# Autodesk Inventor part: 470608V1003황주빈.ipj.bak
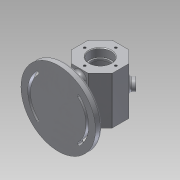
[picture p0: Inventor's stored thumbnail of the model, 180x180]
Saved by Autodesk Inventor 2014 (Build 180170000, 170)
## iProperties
Created: 2017-06
Part Number: 470608V1003황주빈.ipj.bak
Material: Aluminum 6061
Document SubType Name: Modeling
Designer: user
Density: 2.71 g/cm^3
Appearance: Aluminum - Flat
Author: user
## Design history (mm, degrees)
sketch "Sketch2"
  geometry: C1 r 55 at (0, 0); 1 further point
  constraints: 1 centre point, 1 coincident
extrude "Extrusion1" new body sketch "Sketch2" distance "d0" = 10; taper "d1" = 0 deg
sketch "Sketch3"
  geometry: L1 (-55, 0)-(-55, 10) reference; L2 (-55, 10)-(55, 10) reference; L3 (55, 10)-(55, 0) reference; L4 (55, 0)-(-55, 0) reference; L5 (0, 0)-(0, 62); L6 (12.426, 92)-(30, 74.426); L7 (30, 74.426)-(30, 49.574); L8 (30, 49.574)-(12.426, 32); L9 (12.426, 32)-(-12.426, 32); L10 (-12.426, 32)-(-30, 49.574); L11 (-30, 49.574)-(-30, 74.426); L12 (-30, 74.426)-(-12.426, 92); L13 (-12.426, 92)-(12.426, 92); 2 further points
  constraints: 18 end point, 1 midpoint, 17 other
extrude "Extrusion2" join sketch "Sketch3" stored distance "d2" = 70; taper "d3" = 0 deg
sketch "Sketch4"
  geometry: L1 (0, 55)-(10, 55) reference; L2 (10, 55)-(10, -55) reference; L3 (10, -55)-(0, -55) reference; L4 (0, -55)-(0, 55) reference; L5 (92, -35)-(32, -35) reference; L6 (32, -35)-(32, 35) reference; L7 (32, 35)-(92, 35) reference; L8 (92, 35)-(92, -35) reference; L9 (62, 35)-(62, -35); L10 (62, 35)-(78, 35); L11 (78, 35)-(78, 23.3); L12 (76, 23)-(76, 20); L13 (87, 17)-(87, -17); L14 (84, -20)-(76, -20); L15 (76, -20)-(76, -23); L16 (76, -23)-(77.7, -23); L17 (78, -23.3)-(78, -35); L18 (77.7, 23)-(76, 23); L19 (84, 20)-(76, 20); L20 (78, -35)-(62, -35); L21 (62, 35)-(62, -35); A1 r 0.3 centre (77.7, 23.3) between (77.7, 23) and (78, 23.3); A2 r 0.3 centre (77.7, -23.3) between (78, -23.3) and (77.7, -23); A3 r 3 centre (84, 17) between (87, 17) and (84, 20); A4 r 3 centre (84, -17) between (84, -20) and (87, -17); 1 further point
  constraints: 26 end point, 8 point on circle, 8 tangent, 4 centre point, 2 equal radius, 2 midpoint, 2 point on line
  dimensions: "d4" = 0.3 radius of A1; "d5" = 3 radius of A3
revolve "Revolution1" sketch "Sketch4" stored, may be unused: angle "d6" = 90 deg
sketch "Sketch6"
  geometry: L1 (0, 0)-(55, 0.071); L2 (0, 0)-(26.836, 26.905); L3 (33.898, 33.985)-(44.934, 45.049); L4 (26.905, -26.836)-(0, 0); L5 (0, 0)-(26.905, -26.836); L6 (33.985, -33.898)-(47.581, -47.459); L7 (47.581, -47.459)-(33.985, -33.898); L8 (-38.83, -38.952)-(-48.246, -48.396); L9 (0, 0)-(-26.828, -26.912); L10 (0, 0)-(-38, -0.059); L11 (0, 0)-(-26.912, 26.828); A1 r 55 centre (0, 0) between (55, 0.071) and (-38.83, -38.952) reference; A2 r 2 centre (-30.358, -30.453) between (-31.77, -31.869) and (-28.946, -29.037); A3 r 2 centre (-30.453, 30.358) between (-29.037, 28.946) and (-31.869, 31.77); A4 r 2 centre (30.445, -30.367) between (29.029, -28.954) and (31.861, -31.779); A5 r 2 centre (30.367, 30.445) between (31.779, 31.861) and (28.954, 29.029); A6 r 5 centre (30.367, 30.445) between (33.898, 33.985) and (26.836, 26.905); A7 r 41 centre (0, 0) between (29.029, -28.954) and (28.954, 29.029); A8 r 45 centre (0, 0) between (31.861, -31.779) and (31.779, 31.861); A9 r 5 centre (30.445, -30.367) between (26.905, -26.836) and (33.985, -33.898); A10 r 5 centre (-30.358, -30.453) between (-33.888, -33.994) and (-26.828, -26.912); A11 r 41 centre (0, 0) between (-29.037, 28.946) and (-28.946, -29.037); A12 r 45 centre (0, 0) between (-31.869, 31.77) and (-31.77, -31.869); A13 r 5 centre (-30.453, 30.358) between (-26.912, 26.828) and (-33.994, 33.888); A14 r 38 centre (0, 0) between (-26.912, 26.828) and (-26.828, -26.912); A15 r 38 centre (0, 0) between (26.905, -26.836) and (26.836, 26.905); A16 r 48 centre (0, 0) between (-33.994, 33.888) and (-33.888, -33.994); A17 r 48 centre (0, 0) between (33.985, -33.898) and (33.898, 33.985); 1 further point
  constraints: 35 point on circle, 22 end point, 16 centre point, 9 coincident, 2 other
extrude "Extrusion3" cut sketch "Sketch6" distance "d11" = 3; taper "d12" = 0 deg
sketch "Sketch7"
  geometry: C1 r 55 at (0, 0) reference; A1 r 41 centre (0, 0) between (-29.037, 28.946) and (-28.946, -29.037) reference; A2 r 2 centre (-30.358, -30.453) between (-31.77, -31.869) and (-28.946, -29.037) reference; A3 r 45 centre (0, 0) between (-31.869, 31.77) and (-31.77, -31.869) reference; A4 r 2 centre (-30.453, 30.358) between (-29.037, 28.946) and (-31.869, 31.77) reference; A5 r 5 centre (-30.453, 30.358) between (-26.912, 26.828) and (-33.994, 33.888) reference; A6 r 48 centre (0, 0) between (-33.994, 33.888) and (-33.888, -33.994) reference; A7 r 5 centre (-30.358, -30.453) between (-33.888, -33.994) and (-26.828, -26.912) reference; A8 r 38 centre (0, 0) between (-26.912, 26.828) and (-26.828, -26.912) reference; A9 r 41 centre (0, 0) between (29.029, -28.954) and (28.954, 29.029) reference; A10 r 2 centre (30.367, 30.445) between (31.779, 31.861) and (28.954, 29.029) reference; A11 r 45 centre (0, 0) between (31.861, -31.779) and (31.779, 31.861) reference; A12 r 2 centre (30.445, -30.367) between (29.029, -28.954) and (31.861, -31.779) reference; A13 r 5 centre (30.367, 30.445) between (33.898, 33.985) and (26.836, 26.905) reference; A14 r 38 centre (0, 0) between (26.905, -26.836) and (26.836, 26.905) reference; A15 r 5 centre (30.445, -30.367) between (26.905, -26.836) and (33.985, -33.898) reference; A16 r 48 centre (0, 0) between (33.985, -33.898) and (33.898, 33.985) reference; A17 r 2 centre (-30.358, -30.453) between (-31.77, -31.869) and (-28.946, -29.037); A18 r 2 centre (-30.453, 30.358) between (-29.037, 28.946) and (-31.869, 31.77); A19 r 2 centre (30.367, 30.445) between (31.779, 31.861) and (28.954, 29.029); A20 r 2 centre (30.445, -30.367) between (29.029, -28.954) and (31.861, -31.779); A21 r 45 centre (0, 0) between (31.861, -31.779) and (31.779, 31.861); A22 r 45 centre (0, 0) between (-31.869, 31.77) and (-31.77, -31.869); A23 r 41 centre (0, 0) between (29.029, -28.954) and (28.954, 29.029); A24 r 41 centre (0, 0) between (-29.037, 28.946) and (-28.946, -29.037)
  constraints: 16 point on circle, 8 centre point, 6 coincident
extrude "Extrusion4" cut sketch "Sketch7" stored distance "d13" = 3; taper "d14" = 0 deg
workplane "Work Plane1"
sketch "Sketch8"
  geometry: L1 (8.551, 10.352)-(8.551, 60.127); L2 (8.551, 60.127)-(15.756, 60.127); L3 (15.756, 60.127)-(15.756, 10.352); L4 (15.756, 10.352)-(8.551, 10.352); L5 (24.853, 0)-(0, 0) reference; 2 further points
  constraints: 1 point on line, 2 other
emboss "Emboss1" sketch "Sketch8" dims "d16" = 0.5, "d17" = 0
sketch "Sketch9"
  geometry: L1 (-5, -24)-(-5, 24); L2 (5, 24)-(5, -24); A1 r 5 centre (0, -24) between (-5, -24) and (5, -24); A2 r 5 centre (0, 24) between (5, 24) and (-5, 24)
  constraints: 4 end point, 4 point on circle, 2 centre point
extrude "Extrusion5" join sketch "Sketch9" stored distance "d18" = 3; taper "d19" = 0 deg
fillet "Fillet1" dims "d20" = 5
workplane "Work Plane2"
sketch "Sketch10"
  geometry: L1 (-24.853, 70)-(0, 70) reference; L2 (-12.426, 70)-(-12.426, 35); C1 r 8 at (-12.426, 35); 1 further point
  constraints: 2 end point, 1 centre point, 1 coincident, 1 midpoint
extrude "Extrusion6" join sketch "Sketch10" stored distance "d22" = 3; taper "d23" = 0 deg
sketch "Sketch11"
  geometry: C1 r 8 at (0, 0) reference; 2 further points
  constraints: 1 coincident
hole "Hole1" sketch "Sketch11" at (0, 0) diameter "d24" = 8; stored, may be unused: countersink angle "d28" = 90 deg, drill point angle "d30" = 118 deg; dims "d25" = 6, "d26" = 4, "d27" = 2, "d29" = 30
chamfer "Chamfer1" distance "d31" = 1; stored, may be unused: second distance "d32" = 2, angle "d33" = 45 deg
fillet "Fillet2" dims "d34" = 3
sketch "Sketch12"
  geometry: L1 (-32.438, 7)-(-28.279, 7) reference; L2 (-28.279, 7)-(-28.279, 10) reference; L3 (-28.279, 10)-(28.566, 10) reference; L4 (28.566, 10)-(28.566, 7) reference; L5 (28.566, 7)-(32.324, 7) reference; L6 (32.324, 7)-(32.324, 10) reference; L7 (32.324, 10)-(42.426, 10) reference; L8 (42.426, 10)-(42.426, 0) reference; L9 (42.426, 0)-(-42.426, 0) reference; L10 (-42.426, 0)-(-42.426, 10) reference; L11 (-42.426, 10)-(-32.438, 10) reference; L12 (-32.438, 10)-(-32.438, 7) reference; L13 (-12.426, 32)-(-30, 49.574) reference; L14 (-30, 49.574)-(-30, 74.426) reference; L15 (-30, 74.426)-(-12.426, 92) reference; L16 (-12.426, 92)-(12.426, 92) reference; L17 (12.426, 92)-(30, 74.426) reference; L18 (30, 74.426)-(30, 49.574) reference; L19 (30, 49.574)-(12.426, 32) reference; L20 (12.426, 32)-(-12.426, 32) reference; L21 (0, 85)-(0, 39); L22 (23, 62)-(-23, 62); C1 r 16 at (0, 62) reference; A1 r 23 centre (0, 62) between (0, 85) and (0, 39); 5 further points
  constraints: 5 coincident, 4 end point, 4 point on circle, 1 centre point
hole "Hole2" sketch "Sketch12" at (0, 85), (23, 62), (0, 39), (-23, 62) diameter "d35" = 3.459; stored, may be unused: countersink angle "d39" = 90 deg, drill point angle "d41" = 118 deg; dims "d36" = 8, "d37" = 4, "d38" = 2, "d40" = 10
sketch "Sketch13"
  geometry: L1 (0, 85)-(0, 39); L2 (23, 62)-(-23, 62); C1 r 16 at (0, 62) reference; A1 r 23 centre (0, 62) between (0, 85) and (0, 39); 5 further points
  constraints: 5 coincident, 4 end point, 4 point on circle, 1 centre point
hole "Hole3" sketch "Sketch13" at (-23, 62), (0, 39), (23, 62), (0, 85) diameter "d42" = 3.459; stored, may be unused: countersink angle "d46" = 90 deg, drill point angle "d48" = 118 deg; dims "d43" = 8, "d44" = 4, "d45" = 2, "d47" = 10
chamfer "Chamfer2" distance "d49" = 1; stored, may be unused: second distance "d50" = 2, angle "d51" = 45 deg
fillet "Fillet3" dims "d52" = 3
fillet "Fillet4" dims "d53" = 1
body "Solid1"
node "Project Cut Edges1"
node "Project Cut Edges2"
node "Project Cut Edges3"
node "Project Cut Edges4"
node "Project Cut Edges5"
node "Project Cut Edges6"
other parameters: "d7" = 45 deg, "d8" = 45 deg, "d9" = 45 deg, "d10" = 45 deg, "d21" = 7
